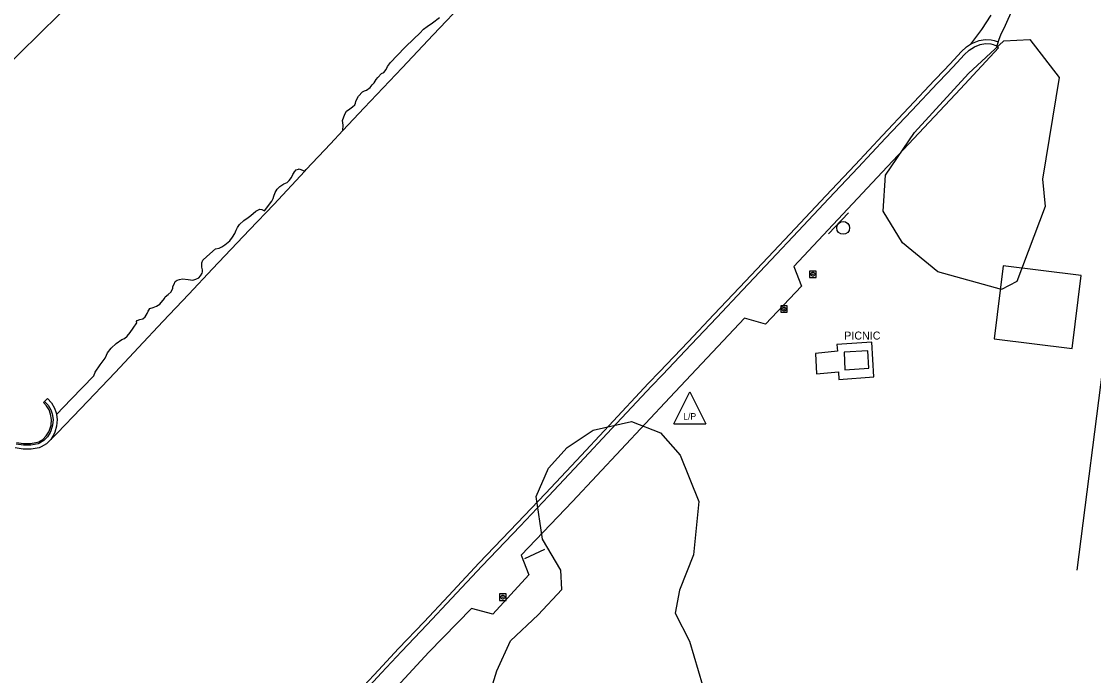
# Model space of a CAD drawing. Extents: x 2161152 to 2175754, y 602179 to 617749.
# Drawn here: x 2163534.2 to 2163869.2, y 605404.6 to 605609 of the extents above; entities that cross this region are included whole.
import ezdxf

# ---------------------------------------------------------------- set-up
doc = ezdxf.new("R2010")
doc.units = 0
for name, color, linetype in [('RD_EX_Bldg', 7, 'Continuous'), ('RD_EX_BldgApp_Sign', 7, 'Continuous'), ('RD_EX_Conc_Curb', 7, 'Continuous'), ('RD_EX_Conc_Gutter', 7, 'Continuous'), ('RD_EX_Conc_Sidewalk', 7, 'Continuous'), ('RD_EX_Conc_Slab', 7, 'Continuous'), ('RD_EX_Misc', 7, 'Continuous'), ('RD_EX_Misc_Golf_Cartpath', 7, 'Continuous'), ('RD_EX_Parking_Asphalt', 7, 'Continuous'), ('RD_EX_Parking_Conc', 7, 'Continuous'), ('RD_EX_Road', 7, 'Continuous'), ('RD_EX_UT', 7, 'Continuous'), ('RD_EX_VEG', 7, 'Continuous')]:
    doc.layers.add(name, color=color, linetype=linetype)

msp = doc.modelspace()

# ---------------------------------------------------------------- linework, layer by layer
at = {"layer": 'RD_EX_Bldg'}
msp.add_lwpolyline([(2163838.2, 605509.83), (2163862.54, 605506.83), (2163865.36, 605529.67), (2163841.01, 605532.67), (2163838.2, 605509.83)], dxfattribs=at)
at = {"layer": 'RD_EX_BldgApp_Sign'}
for p, q in [((2163792.63, 605549.2), (2163786.43, 605542.68)), ((2163691.5, 605441.23), (2163697.8, 605444.12))]:
    msp.add_line(p, q, dxfattribs=at)
msp.add_circle((2163790.98, 605544.53), 2, dxfattribs=at)
at = {"layer": 'RD_EX_Conc_Curb'}
for points in [[(2163637.74, 605395.78), (2163646.73, 605405.44), (2163653, 605412.14), (2163660.94, 605420.52), (2163668.62, 605428.66), (2163678.16, 605438.91), (2163690.06, 605451.3), (2163698.91, 605460.66), (2163708.6, 605470.94), (2163718.71, 605481.82), (2163731.1, 605495.08), (2163734.48, 605498.61), (2163743.49, 605508.04), (2163751.5, 605516.52), (2163759.49, 605525.04), (2163768.47, 605534.51), (2163776.9, 605543.46), (2163786.51, 605553.68), (2163795.63, 605563.38), (2163804.26, 605572.54), (2163812.46, 605581.23), (2163820.42, 605589.76), (2163823.57, 605593.02), (2163826.59, 605596.24), (2163828.82, 605598.61), (2163830.33, 605600.05), (2163831.98, 605601.11), (2163833.8, 605601.82), (2163835.42, 605602.13), (2163837.08, 605602.05), (2163837.81, 605601.88), (2163838.39, 605601.67), (2163838.97, 605601.46)], [(2163532.64, 605477.45), (2163534.85, 605477.09), (2163537.07, 605477.11), (2163539.26, 605477.51), (2163539.59, 605477.65), (2163540.89, 605478.43), (2163541.95, 605479.49), (2163542.73, 605480.81), (2163542.94, 605481.26), (2163543.44, 605482.92), (2163543.56, 605484.63), (2163543.31, 605486.33), (2163542.84, 605487.7), (2163542.07, 605488.95), (2163541.07, 605489.96), (2163541.33, 605490.21), (2163541.43, 605490.31), (2163542.58, 605489.11), (2163543.41, 605487.68), (2163543.8, 605486.45), (2163544.06, 605484.64), (2163543.93, 605482.83), (2163543.41, 605481.08), (2163543.18, 605480.57), (2163542.34, 605479.18), (2163541.2, 605478.04), (2163539.82, 605477.2), (2163539.4, 605477.02), (2163537.12, 605476.61), (2163534.81, 605476.59), (2163532.53, 605476.96)]]:
    msp.add_lwpolyline(points, dxfattribs=at)
at = {"layer": 'RD_EX_Conc_Gutter'}
for points in [[(2163636.8, 605396.66), (2163645.79, 605406.32), (2163652.06, 605413.03), (2163660, 605421.41), (2163667.68, 605429.54), (2163677.22, 605439.8), (2163689.13, 605452.19), (2163697.97, 605461.55), (2163707.66, 605471.83), (2163717.76, 605482.71), (2163730.16, 605495.97), (2163733.55, 605499.51), (2163742.55, 605508.93), (2163750.56, 605517.41), (2163758.55, 605525.93), (2163767.53, 605535.4), (2163775.95, 605544.34), (2163785.57, 605554.56), (2163794.69, 605564.26), (2163803.32, 605573.43), (2163811.52, 605582.12), (2163819.49, 605590.65), (2163822.64, 605593.91), (2163825.64, 605597.13), (2163827.9, 605599.52), (2163829.53, 605601.07), (2163830.82, 605601.91), (2163831.39, 605602.27), (2163833.44, 605603.07), (2163835.33, 605603.43), (2163837.25, 605603.33), (2163838.17, 605603.13), (2163838.83, 605602.89), (2163839.41, 605602.68), (2163838.97, 605601.46)], [(2163541.43, 605490.31), (2163542.34, 605491.17), (2163543.58, 605489.86), (2163544.55, 605488.19), (2163545.02, 605486.73), (2163545.1, 605486.19), (2163545.32, 605484.69), (2163545.16, 605482.6), (2163544.58, 605480.64), (2163544.28, 605479.99), (2163543.33, 605478.41), (2163542.2, 605477.27), (2163541.98, 605477.05), (2163540.38, 605476.08), (2163539.75, 605475.82), (2163537.24, 605475.37), (2163534.71, 605475.34), (2163532.25, 605475.74)]]:
    msp.add_lwpolyline(points, dxfattribs=at)
at = {"layer": 'RD_EX_Conc_Sidewalk'}
msp.add_lwpolyline([(2163838.92, 605601.32), (2163839.57, 605600.83), (2163827.6, 605587.97), (2163801.59, 605560.25), (2163775.52, 605532.5), (2163777.95, 605526.36), (2163766.68, 605514.48), (2163760.12, 605516.28), (2163736.77, 605491.51), (2163706.35, 605459.01), (2163690.36, 605442.26), (2163692.8, 605436.07), (2163681.5, 605423.85), (2163674.83, 605425.58), (2163661.55, 605411.87), (2163638.94, 605387.4)], dxfattribs=at)
at = {"layer": 'RD_EX_Conc_Slab'}
msp.add_lwpolyline([(2163782.34, 605505.27), (2163782.62, 605498.94), (2163789.52, 605499.53), (2163789.64, 605497.12), (2163800.54, 605497.93), (2163799.94, 605508.85), (2163789.04, 605508.11), (2163789.25, 605506.01), (2163782.34, 605505.27)], dxfattribs=at)
at = {"layer": 'RD_EX_Misc'}
for points in [[(2163780.51, 605529.05), (2163782.51, 605529.05), (2163782.51, 605531.05), (2163780.51, 605531.05), (2163780.51, 605529.05)], [(2163780.91, 605530.05), (2163780.93, 605530.2), (2163780.99, 605530.34), (2163781.08, 605530.47), (2163781.2, 605530.56), (2163781.34, 605530.63), (2163781.49, 605530.65), (2163781.64, 605530.64), (2163781.79, 605530.58), (2163781.91, 605530.49), (2163782.01, 605530.38), (2163782.08, 605530.24), (2163782.11, 605530.09), (2163782.11, 605530.05)], [(2163782.11, 605530.05), (2163782.09, 605529.9), (2163782.03, 605529.76), (2163781.94, 605529.63), (2163781.82, 605529.54), (2163781.68, 605529.48), (2163781.53, 605529.45), (2163781.38, 605529.47), (2163781.23, 605529.52), (2163781.11, 605529.61), (2163781.01, 605529.72), (2163780.94, 605529.86), (2163780.91, 605530.01), (2163780.91, 605530.05)], [(2163781.41, 605530.05), (2163781.43, 605530.11), (2163781.48, 605530.15), (2163781.54, 605530.15), (2163781.59, 605530.11), (2163781.61, 605530.05)], [(2163781.61, 605530.05), (2163781.59, 605529.99), (2163781.54, 605529.96), (2163781.48, 605529.96), (2163781.43, 605529.99), (2163781.41, 605530.05)], [(2163771.52, 605518.14), (2163773.52, 605518.14), (2163773.52, 605520.14), (2163771.52, 605520.14), (2163771.52, 605518.14)], [(2163771.92, 605519.14), (2163771.94, 605519.29), (2163771.99, 605519.44), (2163772.09, 605519.56), (2163772.21, 605519.65), (2163772.35, 605519.72), (2163772.5, 605519.74), (2163772.65, 605519.73), (2163772.8, 605519.67), (2163772.92, 605519.59), (2163773.02, 605519.47), (2163773.09, 605519.33), (2163773.12, 605519.18), (2163773.12, 605519.14)], [(2163773.12, 605519.14), (2163773.1, 605518.99), (2163773.04, 605518.85), (2163772.95, 605518.72), (2163772.83, 605518.63), (2163772.69, 605518.57), (2163772.54, 605518.54), (2163772.38, 605518.56), (2163772.24, 605518.61), (2163772.11, 605518.7), (2163772.01, 605518.81), (2163771.95, 605518.95), (2163771.92, 605519.1), (2163771.92, 605519.14)], [(2163772.42, 605519.14), (2163772.44, 605519.2), (2163772.49, 605519.24), (2163772.55, 605519.24), (2163772.6, 605519.2), (2163772.62, 605519.14)], [(2163772.62, 605519.14), (2163772.6, 605519.08), (2163772.55, 605519.05), (2163772.49, 605519.05), (2163772.44, 605519.08), (2163772.42, 605519.14)], [(2163791.29, 605505.71), (2163791.45, 605500.15), (2163798.96, 605500.68), (2163798.68, 605506.05), (2163791.29, 605505.71)], [(2163683.63, 605428.12), (2163685.63, 605428.12), (2163685.63, 605430.12), (2163683.63, 605430.12), (2163683.63, 605428.12)], [(2163684.03, 605429.12), (2163684.05, 605429.27), (2163684.1, 605429.41), (2163684.2, 605429.53), (2163684.32, 605429.63), (2163684.46, 605429.69), (2163684.61, 605429.72), (2163684.76, 605429.7), (2163684.9, 605429.65), (2163685.03, 605429.56), (2163685.13, 605429.44), (2163685.2, 605429.31), (2163685.23, 605429.15), (2163685.23, 605429.12)], [(2163685.23, 605429.12), (2163685.21, 605428.96), (2163685.15, 605428.82), (2163685.06, 605428.7), (2163684.94, 605428.6), (2163684.8, 605428.54), (2163684.65, 605428.52), (2163684.49, 605428.53), (2163684.35, 605428.58), (2163684.22, 605428.67), (2163684.12, 605428.79), (2163684.06, 605428.93), (2163684.03, 605429.08), (2163684.03, 605429.12)], [(2163684.53, 605429.12), (2163684.55, 605429.18), (2163684.6, 605429.21), (2163684.66, 605429.21), (2163684.71, 605429.18), (2163684.73, 605429.12)], [(2163684.73, 605429.12), (2163684.71, 605429.06), (2163684.66, 605429.02), (2163684.6, 605429.02), (2163684.55, 605429.06), (2163684.53, 605429.12)]]:
    msp.add_lwpolyline(points, dxfattribs=at)
at = {"layer": 'RD_EX_Parking_Asphalt'}
for points in [[(2163839.41, 605602.68), (2163840.29, 605604.9), (2163841.67, 605607.92), (2163843.91, 605612.8)], [(2163634.67, 605574.98), (2163634.78, 605576.66), (2163634.57, 605578.08), (2163634.96, 605579.2), (2163635.39, 605580.26), (2163635.79, 605581.05), (2163636.83, 605581.76), (2163637.61, 605582.31), (2163638.38, 605582.98), (2163638.57, 605583.48), (2163638.65, 605584), (2163638.85, 605584.57), (2163639.56, 605585.65), (2163640.79, 605587.04), (2163641.4, 605587.39), (2163642.05, 605587.58), (2163643.16, 605588.38), (2163643.75, 605589.22), (2163644.39, 605589.88), (2163645.09, 605590.86), (2163645.6, 605591.56), (2163646.67, 605592.76), (2163647.49, 605593.14), (2163648.21, 605594.06), (2163648.63, 605594.99), (2163649.52, 605596.24), (2163651.6, 605598.41), (2163654.13, 605601.05), (2163656.86, 605603.59), (2163658.66, 605605.38), (2163659.83, 605606.62), (2163661.01, 605607.46), (2163662.6, 605608.64), (2163664.84, 605610.33)], [(2163545.1, 605486.19), (2163549.74, 605491.01), (2163556.85, 605498.32), (2163557.21, 605499.43), (2163558.77, 605501.7), (2163560.35, 605503.76), (2163560.81, 605504.75), (2163561.1, 605505.51), (2163562.19, 605506.93), (2163563.8, 605508.39), (2163565.55, 605509.65), (2163566.37, 605509.98), (2163567.28, 605510.69), (2163568.17, 605511.83), (2163569.09, 605513.15), (2163570.2, 605514.81), (2163570.16, 605515.23), (2163570.31, 605515.63), (2163571.16, 605515.92), (2163572.11, 605516.1), (2163572.89, 605516.76), (2163573.45, 605517.72), (2163573.82, 605518.46), (2163574.03, 605518.86), (2163574.36, 605519.37), (2163575.34, 605519.65), (2163576.39, 605520.05), (2163577.42, 605520.71), (2163578.9, 605522.43), (2163579.1, 605523), (2163580.02, 605523.7), (2163580.93, 605524.59), (2163581.48, 605525.64), (2163581.53, 605526.19), (2163581.89, 605526.98), (2163582.27, 605527.75), (2163582.83, 605528.17), (2163583.63, 605528.4), (2163584.53, 605528.64), (2163586.29, 605528.39), (2163587.74, 605528.22), (2163588.72, 605528.45), (2163589.61, 605528.89), (2163590.15, 605529.55), (2163590.7, 605530.33), (2163590.78, 605530.84), (2163590.79, 605531.37), (2163590.58, 605532.27), (2163590.52, 605532.87), (2163590.53, 605533.59), (2163590.9, 605534.41), (2163592.14, 605535.63), (2163594.87, 605538), (2163595.93, 605538.21), (2163596.8, 605538.58), (2163597.8, 605539.25), (2163599.28, 605540.49), (2163600.19, 605541.67), (2163600.87, 605542.72), (2163601.32, 605543.8), (2163601.7, 605544.65), (2163602.36, 605545.63), (2163603.67, 605546.81), (2163605, 605547.77), (2163605.84, 605548.44), (2163607.43, 605549.74), (2163608.67, 605550.33), (2163609.29, 605550.31), (2163610.1, 605549.87), (2163612.46, 605552.84), (2163612.85, 605553.68), (2163613.03, 605554.41), (2163613.49, 605555.58), (2163614.07, 605556.58), (2163614.92, 605557.47), (2163616.22, 605558.32), (2163617.25, 605558.76), (2163617.9, 605559.3), (2163618.55, 605560.31), (2163618.95, 605561.19), (2163619.16, 605561.5), (2163619.54, 605562.07), (2163620.08, 605562.65), (2163620.74, 605562.93), (2163621.01, 605563), (2163622.75, 605562.26)]]:
    msp.add_lwpolyline(points, dxfattribs=at)
at = {"layer": 'RD_EX_Parking_Conc'}
for points in [[(2163543.33, 605478.41), (2163545.39, 605480.37), (2163552.72, 605488.11), (2163563.45, 605499.35), (2163570.74, 605507.1), (2163578.38, 605515.29), (2163586.52, 605523.85), (2163593.85, 605531.7), (2163605.45, 605543.95), (2163613.07, 605551.88), (2163622.75, 605562.26), (2163623.22, 605562.76), (2163630.73, 605570.79), (2163634.67, 605574.98), (2163641.34, 605582.08), (2163653.14, 605594.57), (2163662.87, 605604.88), (2163673.17, 605615.77)], [(2163837.16, 605611), (2163834.19, 605606.53), (2163830.82, 605601.91)]]:
    msp.add_lwpolyline(points, dxfattribs=at)
at = {"layer": 'RD_EX_Road'}
msp.add_lwpolyline([(2163527.46, 605593.1), (2163545.95, 605611.18), (2163564.23, 605628.79), (2163582.96, 605646.73), (2163603.07, 605666.54), (2163628.34, 605690.96), (2163653.38, 605714.88), (2163674.12, 605734.52), (2163696.8, 605756.06), (2163717.71, 605775.93), (2163724.24, 605782.35), (2163738.69, 605796.14), (2163760.25, 605816.27), (2163783.41, 605837.78), (2163799.79, 605852.86), (2163824.9, 605876.09), (2163849.76, 605899.1), (2163872.57, 605920.04)], dxfattribs=at)
at = {"layer": 'RD_EX_UT'}
for p, q in [((2163738.02, 605483.33), (2163743.02, 605493.33)), ((2163743.02, 605493.33), (2163748.02, 605483.33)), ((2163738.02, 605483.33), (2163748.02, 605483.33))]:
    msp.add_line(p, q, dxfattribs=at)
at = {"layer": 'RD_EX_VEG'}
for points in [[(2163853.29, 605559.74), (2163854.12, 605551.21), (2163845.3, 605527.75), (2163840.43, 605525.27), (2163820.58, 605530.74), (2163809.57, 605539.88), (2163803.53, 605549.8), (2163804.26, 605560.98), (2163813.24, 605574.39), (2163830.1, 605592.82), (2163841.23, 605602.99), (2163849.28, 605603.37), (2163858.5, 605591.5), (2163853.29, 605559.74)], [(2163864.06, 605437.55), (2163872.74, 605505.22)], [(2163678.9, 605393.57), (2163682.75, 605406.09), (2163687.04, 605415.44), (2163695.65, 605423.63), (2163703.02, 605431.54), (2163702.78, 605437.6), (2163697.06, 605447.26), (2163695.04, 605460.62), (2163698.89, 605469.41), (2163704.71, 605475.87), (2163712.9, 605481.33), (2163724.82, 605484.01), (2163733.93, 605480.46), (2163740.08, 605473.45), (2163745.85, 605459.05), (2163744.23, 605442.32), (2163739.81, 605431.27), (2163738.43, 605424.14), (2163742.91, 605415.33), (2163746.97, 605401.63)]]:
    msp.add_lwpolyline(points, dxfattribs=at)

# ---------------------------------------------------------------- texts
at = {"layer": 'RD_EX_Misc_Golf_Cartpath'}
msp.add_text('PICNIC', height=2.5, dxfattribs=at).set_placement((2163791.31, 605509.62))
at = {"layer": 'RD_EX_UT'}
msp.add_text('L/P', height=2, dxfattribs=at).set_placement((2163741.02, 605484.62))

doc.saveas('drawing.dxf')
